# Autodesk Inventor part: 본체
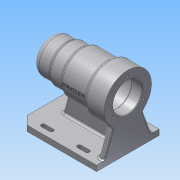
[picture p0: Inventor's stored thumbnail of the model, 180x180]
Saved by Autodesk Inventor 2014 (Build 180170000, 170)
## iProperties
Created: 2017-09
Part Number: 본체
Material: 알루미늄 6061
Document SubType Name: Modeling
Designer: user
Density: 2.71 g/cm^3
Appearance: 알루미늄 - 평지
Mass: 700.2 g
Surface Area: 709.663 cm^2
Volume: 258.376 cm^3
Author: user
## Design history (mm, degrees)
sketch "스케치1"
  geometry: L1 (56, 45)-(-56, 45); L2 (-56, 45)-(-56, -45); L3 (-56, -45)-(56, -45); L4 (56, -45)-(56, 45); L5 (56, 45)-(-56, -45); L6 (-56, 45)-(56, -45); 1 further point
  constraints: 12 end point, 2 midpoint, 2 parallel, 1 horizontal, 1 perpendicular
  dimensions: "d0" = 112 distance of L2.end L3.end; "d1" = 90 distance of L1.end L2.end
extrude "돌출1" new body sketch "스케치1" distance "d2" = 8; taper "d3" = 0 deg
sketch "스케치2"
  geometry: C1 r 34 at (45, 70); 1 further point
  constraints: 1 centre point, 1 vertical alignment
  dimensions: "d4" = 70 distance of point (45, 0) C1.centre; "d5" = 68 diameter of C1
extrude "돌출2" join sketch "스케치2" distance "d6" = 28; taper "d7" = 0 deg
sketch "스케치3"
  geometry: C1 r 34 at (0, 0) reference; C2 r 30 at (0, 0); 1 further point
  constraints: 1 centre point, 1 coincident
  dimensions: "d8" = 60 diameter of C2
extrude "돌출3" join sketch "스케치3" distance "d9" = 39; taper "d10" = 0 deg
sketch "스케치4"
  geometry: C1 r 30 at (0, 0) reference; C2 r 27 at (0, 0); 1 further point
  constraints: 1 centre point, 1 coincident
  dimensions: "d11" = 54 diameter of C2
extrude "돌출4" join sketch "스케치4" distance "d12" = 20; taper "d13" = 0 deg
sketch "스케치5"
  geometry: C1 r 27 at (0, 0) reference; C2 r 25 at (0, 0); 1 further point
  constraints: 1 centre point, 1 coincident
  dimensions: "d14" = 50 diameter of C2
extrude "돌출5" join sketch "스케치5" distance "d15" = 25; taper "d16" = 0 deg
chamfer "모따기1" distance "d17" = 12; stored, may be unused: second distance "d18" = 2, angle "d19" = 45 deg
fillet "모깎기1" dims "d20" = 3
fillet "모깎기2" dims "d21" = 9
sketch "스케치6"
  geometry: C1 r 34 at (0, 0) reference; C2 r 21 at (0, 0); 1 further point
  constraints: 1 centre point, 1 coincident
  dimensions: "d22" = 42 diameter of C2
extrude "돌출6" cut sketch "스케치6" distance "d23" = 15; taper "d24" = 0 deg
sketch "스케치7"
  geometry: C1 r 21 at (0, 0) reference; C2 r 24 at (0, 0); 1 further point
  constraints: 1 centre point, 1 coincident
  dimensions: "d25" = 48 diameter of C2
extrude "돌출7" cut sketch "스케치7" distance "d26" = 54; taper "d27" = 0 deg
sketch "스케치8"
  geometry: C1 r 21 at (0, 0) reference; C2 r 21 at (0, 0); 1 further point
  constraints: 1 centre point, 1 coincident
  dimensions: "d28" = 42 diameter of C2
extrude "돌출8" cut sketch "스케치8" distance "d29" = 12; taper "d30" = 0 deg
sketch "스케치9"
  geometry: C1 r 21 at (0, 0) reference; C2 r 17.5 at (0, 0); 1 further point
  constraints: 1 centre point, 1 coincident
  dimensions: "d31" = 35 diameter of C2
extrude "돌출9" cut sketch "스케치9" distance "d32" = 18; taper "d33" = 0 deg
sketch "스케치10"
  geometry: C1 r 25 at (0, 0) reference; C2 r 16 at (0, 0); 1 further point
  constraints: 1 centre point, 1 coincident
  dimensions: "d34" = 32 diameter of C2
extrude "돌출10" cut sketch "스케치10" distance "d35" = 4; taper "d36" = 0 deg
sketch "스케치11"
  geometry: C1 r 16 at (0, 0) reference; C2 r 10.5 at (0, 0); 1 further point
  constraints: 1 centre point, 1 coincident
  dimensions: "d37" = 21 diameter of C2
extrude "돌출11" cut sketch "스케치11" distance "d38" = 3; taper "d39" = 0 deg
fillet "모깎기3" dims "d40" = 3
chamfer "모따기2" distance "d41" = 1; stored, may be unused: second distance "d42" = 2, angle "d43" = 45 deg; dims "d16" = 0
sketch "스케치12"
  geometry: L1 (0, 26)-(0, 0); L2 (0, 0)-(-22.517, -13); C1 r 34 at (0, 0) reference; A1 r 26 centre (0, 0) between (0, 26) and (-22.517, -13); 3 further points
  constraints: 4 end point, 2 coincident, 2 point on circle, 1 centre point, 1 symmetric about line, 1 vertical, 1 vertical alignment
  dimensions: "d44" = 52 diameter of A1; "d45" = 120 deg angle of L1 L2
hole "구멍1" sketch "스케치12" at (0, 26), (-22.517, -13), (22.517, -13) diameter "d46" = 3.242; stored, may be unused: countersink angle "d50" = 90 deg, drill point angle "d52" = 118 deg; dims "d47" = 8, "d48" = 4, "d49" = 2, "d51" = 11
sketch "스케치13"
  geometry: L1 (-32, -34)-(-20, -34); L2 (-32, -36.886)-(-20, -36.886); L3 (-20, -31.114)-(-32, -31.114); L4 (20, -34)-(32, -34); L5 (20, -36.886)-(32, -36.886); L6 (32, -31.114)-(20, -31.114); L7 (56, -45)-(56, 45) reference; L8 (0, 0)-(-17.114, 0); L9 (20, 34)-(32, 34); L10 (20, 36.886)-(32, 36.886); L11 (32, 31.114)-(20, 31.114); L12 (-32, 34)-(-20, 34); L13 (-32, 36.886)-(-20, 36.886); L14 (-20, 31.114)-(-32, 31.114); A1 r 2.886 centre (-32, -34) between (-32, -31.114) and (-32, -36.886); A2 r 2.886 centre (-20, -34) between (-20, -36.886) and (-20, -31.114); A3 r 2.886 centre (20, -34) between (20, -31.114) and (20, -36.886); A4 r 2.886 centre (32, -34) between (32, -36.886) and (32, -31.114); A5 r 2.886 centre (32, 34) between (32, 31.114) and (32, 36.886); A6 r 2.886 centre (20, 34) between (20, 36.886) and (20, 31.114); A7 r 2.886 centre (-32, 34) between (-32, 36.886) and (-32, 31.114); A8 r 2.886 centre (-20, 34) between (-20, 31.114) and (-20, 36.886); 4 further points
  constraints: 34 end point, 16 point on circle, 14 symmetric about line, 8 centre point, 8 tangent, 4 point on line, 2 midpoint, 2 parallel, 1 horizontal, 1 perpendicular, 4 other
  dimensions: "d53" = 12 distance of L4.end L4.start; "d54" = 34 vertical distance of L8.start point (26, -34); "d56" = 24 distance from line of L4.end L7; "d57" = 40 distance of L1.end L4.start; "d58" = 12 distance of L1.end L1.start
extrude "돌출12" cut sketch "스케치13" stored distance "d59" = 3; taper "d60" = 0 deg
sketch "스케치14"
  geometry: L1 (0, 8)-(12, 8) reference; L2 (78, 8)-(90, 8) reference; L3 (78, 8)-(12, 8) reference; L4 (0, 0)-(0, 8) reference; L5 (90, 8)-(90, 0) reference; L6 (80, 8)-(66.9, 43.992); L7 (10, 8)-(23.1, 43.992); L8 (10, 8)-(80, 8); A1 r 34 centre (45, 70) between (66.9, 43.992) and (23.1, 43.992) reference; A2 r 34 centre (45, 70) between (23.1, 43.992) and (66.9, 43.992); 1 further point
  constraints: 6 end point, 4 point on circle, 2 point on line, 1 centre point, 1 coincident, 1 collinear, 1 concentric
  dimensions: "d62" = 10 distance from line of L5 L6.start; "d63" = 110 deg angle of L2 L6; "d64" = 10 distance from line of L4 L7.start; "d65" = 110 deg angle of L1 L7
extrude "돌출13" join sketch "스케치14" distance "d66" = 8; taper "d67" = 0 deg
sketch "스케치16"
  geometry: L1 (-56, 54)-(-56, 86) reference; L2 (-47, 95)-(-32.644, 95) reference; L3 (-28.172, 97)-(-13.196, 97) reference; L4 (-8, 100)-(25.343, 100) reference; L5 (31, 104)-(56, 104) reference; L6 (56, 104)-(56, 97.621) reference; L7 (56, 97.621)-(45, 97.621) reference; L8 (45, 97.621)-(44.026, 96) reference; L9 (44.026, 96)-(45, 94.379) reference; L10 (45, 94.379)-(56, 94.379) reference; L11 (56, 94.379)-(56, 92) reference; L12 (56, 92)-(55, 91) reference; L13 (55, 91)-(41, 91) reference; L14 (38, 94)-(-10, 94) reference; L15 (-13, 91)-(-25, 91) reference; L16 (-25, 91)-(-25, 87.5) reference; L17 (-25, 87.5)-(-43, 87.5) reference; L18 (-43, 87.5)-(-43, 86) reference; L19 (-43, 86)-(-47, 86) reference; L20 (-47, 86)-(-47, 80.5) reference; L21 (-50, 77.5)-(-50, 62.5) reference; L22 (-47, 59.5)-(-47, 54) reference; L23 (-47, 54)-(-43, 54) reference; L24 (-43, 54)-(-43, 52.5) reference; L25 (-43, 52.5)-(-25, 52.5) reference; L26 (-25, 52.5)-(-25, 49) reference; L27 (-25, 49)-(-13, 49) reference; L28 (-10, 46)-(38, 46) reference; L29 (41, 49)-(55, 49) reference; L30 (55, 49)-(56, 48) reference; L31 (56, 48)-(56, 0) reference; L32 (56, 0)-(-56, 0) reference; L33 (-56, 0)-(-56, 8) reference; L34 (-56, 8)-(48, 8) reference; L35 (48, 8)-(48, 36) reference; L36 (48, 36)-(31, 36) reference; L37 (25.343, 40)-(-8, 40) reference; L38 (-13.196, 43)-(-28.172, 43) reference; L39 (-32.644, 45)-(-47, 45) reference; L40 (-34, 8)-(-24.089, 44.988); L41 (-34, 8)-(51.518, 8); L42 (51.518, 8)-(51.518, 44.988); L43 (-24.089, 44.988)-(51.518, 44.988); A1 r 9 centre (-47, 54) between (-56, 54) and (-47, 45) reference; A2 r 9 centre (-47, 86) between (-47, 95) and (-56, 86) reference; A3 r 3 centre (-32.644, 98) between (-32.644, 95) and (-30.408, 96) reference; A4 r 3 centre (-28.172, 94) between (-28.172, 97) and (-30.408, 96) reference; A5 r 3 centre (-13.196, 100) between (-13.196, 97) and (-10.598, 98.5) reference; A6 r 3 centre (-8, 97) between (-8, 100) and (-10.598, 98.5) reference; A7 r 3 centre (31, 101) between (31, 104) and (28.172, 102) reference; A8 r 3 centre (38, 91) between (41, 91) and (38, 94) reference; A9 r 3 centre (-10, 91) between (-10, 94) and (-13, 91) reference; A10 r 3 centre (-47, 77.5) between (-47, 80.5) and (-50, 77.5) reference; A11 r 3 centre (-47, 62.5) between (-50, 62.5) and (-47, 59.5) reference; A12 r 3 centre (-10, 49) between (-13, 49) and (-10, 46) reference; A13 r 3 centre (38, 49) between (38, 46) and (41, 49) reference; A14 r 3 centre (31, 39) between (28.172, 38) and (31, 36) reference; A15 r 3 centre (-8, 43) between (-10.598, 41.5) and (-8, 40) reference; A16 r 3 centre (-13.196, 40) between (-10.598, 41.5) and (-13.196, 43) reference; A17 r 3 centre (-28.172, 46) between (-30.408, 44) and (-28.172, 43) reference; A18 r 3 centre (-32.644, 42) between (-30.408, 44) and (-32.644, 45) reference; 1 further point
  constraints: 8 end point, 2 perpendicular, 2 point on line, 2 other
  dimensions: "d74" = 22 distance from line of L33 L40.start; "d76" = 105 deg angle of L34 L40
extrude "돌출15" join sketch "스케치16" stored distance "d77" = 8; taper "d78" = 0 deg
fillet "모깎기4" dims "d79" = 3
fillet "모깎기5" dims "d80" = 3
fillet "모깎기6" dims "d81" = 3
node "작업 평면3"
sketch "스케치18"
  geometry: L1 (28, -70)-(-72, -70) reference; L2 (28, -22)-(28, 22) reference; 2 further points
  constraints: 1 other
  dimensions: "d86" = 70 distance from line of L1 point (-20, 0); "d87" = 48 distance from line of L2 point (-20, 0)
feature "엠보싱2" sketch "스케치18" dims "d0" = 112, "d1" = 90, "d88" = 0.5, "d89" = 0
fillet "모깎기7" dims "d90" = 0.3
node "솔리드1"
node "절단 모서리 투영2"
other parameters: "d70" = 105 deg
